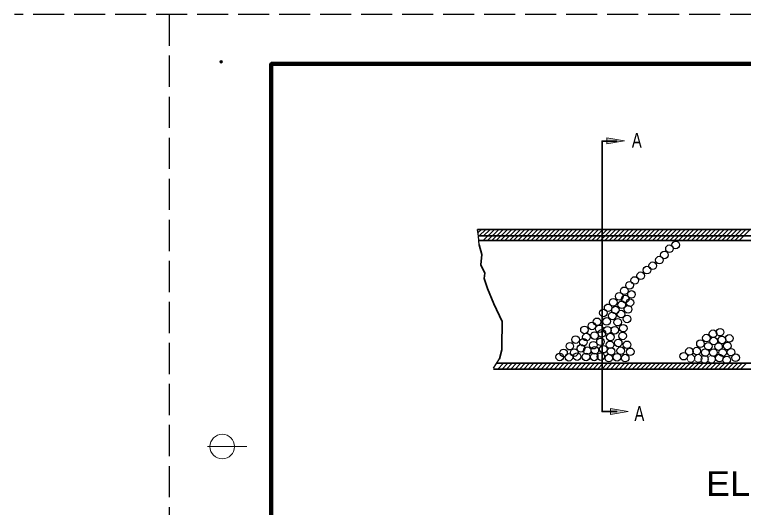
# Model space of a CAD drawing. Extents: x 36 to 71.3, y 0.3 to 22.3.
# Drawn here: x 35.97 to 43.4, y 17.3 to 22.32 of the extents above; entities that cross this region are included whole.
import ezdxf

# ---------------------------------------------------------------- set-up
doc = ezdxf.new("R2010")
doc.units = 0
doc.header["$LTSCALE"] = 0.053
doc.header["$PDMODE"] = 32
doc.header["$PDSIZE"] = 0.0265
doc.linetypes.add('LONG_DASHED', pattern=[7.5, 6, -1.5])
doc.layers.add('1', color=7, linetype='Continuous', lineweight=13)
doc.layers.add('2', color=7, linetype='Continuous', lineweight=13)

msp = doc.modelspace()

# ---------------------------------------------------------------- hatches: boundary and pattern name
at = {"layer": '2'}
for points in [[(42.00942, 21.06925), (42.00942, 21.00925), (42.18942, 21.03925), (42.18942, 21.03925)], [(42.04767, 18.31033), (42.04767, 18.25033), (42.22767, 18.28033), (42.22767, 18.28033)]]:
    msp.add_hatch(color=256, dxfattribs=at).paths.add_polyline_path(points)

# ---------------------------------------------------------------- linework, layer by layer
at = {"layer": '1', "linetype": 'LONG_DASHED', "lineweight": 25}
for p, q in [((71.17325, 22.32408), (35.97325, 22.32408)), ((37.54825, 22.32408), (37.54825, 0.32408))]:
    msp.add_line(p, q, dxfattribs=at)
at = {"layer": '1', "lineweight": 158}
for p, q in [((38.58992, 21.82408), (38.58992, 0.82408)), ((52.503, 21.82408), (38.58992, 21.82408))]:
    msp.add_line(p, q, dxfattribs=at)
at = {"layer": '1', "lineweight": 35}
for p, q in [((40.6925, 20.13667), (48.36025, 20.13667)), ((40.70233, 20.07117), (45.51333, 20.07117)), ((40.71125, 20.024), (45.51333, 20.024)), ((43.68442, 18.77233), (40.88925, 18.77233)), ((43.65142, 18.7125), (40.85458, 18.7125))]:
    msp.add_line(p, q, dxfattribs=at)
at = {"layer": '1', "lineweight": 25}
for p, q in [((40.698, 20.10333), (40.73142, 20.13667)), ((40.71008, 20.07117), (40.77558, 20.13667)), ((40.75133, 20.024), (40.864, 20.13667)), ((40.75425, 20.07117), (40.81975, 20.13667)), ((40.7955, 20.024), (40.90817, 20.13667)), ((40.83967, 20.024), (40.95233, 20.13667)), ((40.88392, 20.024), (40.99658, 20.13667)), ((40.92808, 20.024), (41.04075, 20.13667)), ((40.97225, 20.024), (41.08492, 20.13667)), ((41.0165, 20.024), (41.12917, 20.13667)), ((41.06067, 20.024), (41.17333, 20.13667)), ((41.10483, 20.024), (41.2175, 20.13667)), ((41.14908, 20.024), (41.26175, 20.13667)), ((41.19325, 20.024), (41.30592, 20.13667)), ((41.23742, 20.024), (41.35008, 20.13667)), ((41.28158, 20.024), (41.39425, 20.13667)), ((41.32583, 20.024), (41.4385, 20.13667)), ((41.37, 20.024), (41.48267, 20.13667)), ((41.41417, 20.024), (41.52683, 20.13667)), ((41.45842, 20.024), (41.57108, 20.13667)), ((41.50258, 20.024), (41.61525, 20.13667)), ((41.54675, 20.024), (41.65942, 20.13667)), ((41.591, 20.024), (41.70367, 20.13667)), ((41.63517, 20.024), (41.74783, 20.13667)), ((41.67933, 20.024), (41.792, 20.13667)), ((41.72358, 20.024), (41.83625, 20.13667)), ((41.76775, 20.024), (41.88042, 20.13667)), ((41.81192, 20.024), (41.92458, 20.13667)), ((41.85617, 20.024), (41.96883, 20.13667)), ((41.90033, 20.024), (42.013, 20.13667)), ((41.9445, 20.024), (42.05717, 20.13667)), ((41.98875, 20.024), (42.10142, 20.13667)), ((42.03292, 20.024), (42.14558, 20.13667)), ((42.07708, 20.024), (42.18975, 20.13667)), ((42.12133, 20.024), (42.234, 20.13667)), ((42.1655, 20.024), (42.27817, 20.13667)), ((42.20967, 20.024), (42.32233, 20.13667)), ((42.25392, 20.024), (42.36658, 20.13667)), ((42.29808, 20.024), (42.41075, 20.13667)), ((42.34225, 20.024), (42.45492, 20.13667)), ((42.3865, 20.024), (42.49917, 20.13667)), ((42.43067, 20.024), (42.54333, 20.13667)), ((42.47483, 20.024), (42.5875, 20.13667)), ((42.51908, 20.024), (42.63175, 20.13667)), ((42.56325, 20.024), (42.67592, 20.13667)), ((42.60742, 20.024), (42.72008, 20.13667)), ((42.65167, 20.024), (42.76433, 20.13667)), ((42.69583, 20.024), (42.8085, 20.13667)), ((42.74, 20.024), (42.85267, 20.13667)), ((42.78425, 20.024), (42.89692, 20.13667)), ((42.82842, 20.024), (42.94108, 20.13667)), ((42.87258, 20.024), (42.98525, 20.13667)), ((42.91683, 20.024), (43.0295, 20.13667)), ((42.961, 20.024), (43.07367, 20.13667)), ((43.00517, 20.024), (43.11783, 20.13667)), ((43.04942, 20.024), (43.16208, 20.13667)), ((43.09358, 20.024), (43.20625, 20.13667)), ((43.13775, 20.024), (43.25042, 20.13667)), ((43.182, 20.024), (43.29467, 20.13667)), ((43.22617, 20.024), (43.33883, 20.13667)), ((43.27033, 20.024), (43.383, 20.13667)), ((43.31458, 20.024), (43.42725, 20.13667)), ((43.35875, 20.024), (43.47142, 20.13667)), ((40.85458, 18.724), (40.91533, 18.81817)), ((40.89817, 18.7125), (40.958, 18.77233)), ((40.94242, 18.7125), (41.00225, 18.77233)), ((40.98658, 18.7125), (41.04642, 18.77233)), ((41.03075, 18.7125), (41.09058, 18.77233)), ((41.075, 18.7125), (41.13483, 18.77233)), ((41.11917, 18.7125), (41.179, 18.77233)), ((41.16333, 18.7125), (41.22317, 18.77233)), ((41.20758, 18.7125), (41.26742, 18.77233)), ((41.25175, 18.7125), (41.31158, 18.77233)), ((41.29592, 18.7125), (41.35575, 18.77233)), ((41.34017, 18.7125), (41.4, 18.77233)), ((41.38433, 18.7125), (41.44417, 18.77233)), ((41.4285, 18.7125), (41.48833, 18.77233)), ((41.47275, 18.7125), (41.53258, 18.77233)), ((41.51692, 18.7125), (41.57675, 18.77233)), ((41.56108, 18.7125), (41.62092, 18.77233)), ((41.60533, 18.7125), (41.66517, 18.77233)), ((41.6495, 18.7125), (41.70933, 18.77233)), ((41.69367, 18.7125), (41.7535, 18.77233)), ((41.73792, 18.7125), (41.79775, 18.77233)), ((41.78208, 18.7125), (41.84192, 18.77233)), ((41.82625, 18.7125), (41.88608, 18.77233)), ((41.8705, 18.7125), (41.93033, 18.77233)), ((41.91467, 18.7125), (41.9745, 18.77233)), ((41.95883, 18.7125), (42.01867, 18.77233)), ((42.00308, 18.7125), (42.06292, 18.77233)), ((42.04725, 18.7125), (42.10708, 18.77233)), ((42.09142, 18.7125), (42.15125, 18.77233)), ((42.13567, 18.7125), (42.1955, 18.77233)), ((42.17983, 18.7125), (42.23967, 18.77233)), ((42.224, 18.7125), (42.28383, 18.77233)), ((42.26825, 18.7125), (42.32808, 18.77233)), ((42.31242, 18.7125), (42.37225, 18.77233)), ((42.35658, 18.7125), (42.41642, 18.77233)), ((42.40083, 18.7125), (42.46067, 18.77233)), ((42.445, 18.7125), (42.50483, 18.77233)), ((42.48917, 18.7125), (42.549, 18.77233)), ((42.53342, 18.7125), (42.59317, 18.77233)), ((42.57758, 18.7125), (42.63742, 18.77233)), ((42.62175, 18.7125), (42.68158, 18.77233)), ((42.666, 18.7125), (42.72575, 18.77233)), ((42.71017, 18.7125), (42.77, 18.77233)), ((42.75433, 18.7125), (42.81417, 18.77233)), ((42.79858, 18.7125), (42.85833, 18.77233)), ((42.84275, 18.7125), (42.90258, 18.77233)), ((42.88692, 18.7125), (42.94675, 18.77233)), ((42.93117, 18.7125), (42.99092, 18.77233)), ((42.97533, 18.7125), (43.03517, 18.77233)), ((43.0195, 18.7125), (43.07933, 18.77233)), ((43.06375, 18.7125), (43.1235, 18.77233)), ((43.10792, 18.7125), (43.16775, 18.77233)), ((43.15208, 18.7125), (43.21192, 18.77233)), ((43.19633, 18.7125), (43.25608, 18.77233)), ((43.2405, 18.7125), (43.30033, 18.77233)), ((43.28467, 18.7125), (43.3445, 18.77233)), ((43.32892, 18.7125), (43.38867, 18.77233)), ((43.37308, 18.7125), (43.43292, 18.77233))]:
    msp.add_line(p, q, dxfattribs=at)
at = {"layer": '1'}
msp.add_line((38.33992, 17.92408), (37.93992, 17.92408), dxfattribs=at)
at = {"layer": '1', "lineweight": 25}
msp.add_lwpolyline([(40.70875, 19.9775), (40.7035, 20.06792), (40.69308, 20.13533)], dxfattribs=at)
at = {"layer": '1', "lineweight": 35}
msp.add_lwpolyline([(40.91533, 18.81817), (40.94133, 18.9085), (40.94133, 18.99125), (40.94133, 19.02175), (40.94483, 19.1185), (40.94483, 19.19867), (40.858, 19.37808), (40.79375, 19.53342), (40.76083, 19.63517), (40.76775, 19.69117), (40.72608, 19.77392), (40.73475, 19.87958), (40.70875, 19.9775)], dxfattribs=at)
at = {"layer": '1', "lineweight": 25}
for centre in [(42.71308, 19.9775), (42.59675, 19.87575), (42.64883, 19.93933), (42.54642, 19.82358), (42.47867, 19.76625), (42.35542, 19.6645), (42.41967, 19.72175), (42.29467, 19.61608), (42.18875, 19.5105), (42.24258, 19.5665), (42.13667, 19.4545), (42.19742, 19.42775), (42.26167, 19.47358), (42.07592, 19.39342), (42.16267, 19.36792), (42.246, 19.39083), (41.97517, 19.28525), (42.02383, 19.33742), (42.0985, 19.3145), (42.22692, 19.32208), (42.0655, 19.25467), (42.15575, 19.27375), (42.2165, 19.22417), (41.85892, 19.15283), (41.911, 19.19483), (42.00817, 19.19867), (42.121, 19.191), (42.17833, 19.12992), (41.7825, 19.11217), (41.9335, 19.12358), (41.95958, 19.07775), (42.01683, 19.10833), (42.0915, 19.10833), (43.09325, 19.07392), (43.16442, 19.08925), (41.69225, 19.01417), (41.77208, 18.98742), (41.80158, 19.03958), (41.88492, 19.05483), (41.94567, 18.99125), (42.04642, 19.03958), (42.17142, 19.05108), (43.02558, 19.02942), (43.10017, 18.99883), (43.1835, 19.01033), (43.25817, 19.02558), (41.63317, 18.94667), (41.746, 18.92375), (41.87275, 18.95683), (41.97517, 18.91617), (42.04292, 18.96067), (42.12625, 18.97975), (42.2165, 18.96067), (42.96475, 18.97217), (43.04467, 18.94667), (43.14883, 18.94283), (43.23908, 18.94925), (41.53075, 18.83725), (41.56892, 18.878), (41.6245, 18.83342), (41.67833, 18.88175), (41.70783, 18.84108), (41.79808, 18.83725), (41.81025, 18.90083), (41.88142, 18.83725), (41.88842, 18.90467), (41.94917, 18.84108), (42.05333, 18.89325), (42.11408, 18.83342), (42.15225, 18.90083), (42.2495, 18.88942), (42.79467, 18.84483), (42.85192, 18.89325), (42.92658, 18.89708), (43.01342, 18.88175), (43.09675, 18.88175), (43.1905, 18.88175), (43.27725, 18.88558), (42.03075, 18.82575), (42.19742, 18.82575), (43.1575, 18.82575), (43.23217, 18.80667), (43.32242, 18.82958)]:
    msp.add_circle(centre, 0.03866, dxfattribs=at)
at = {"layer": '1'}
for centre, radius in [((42.86758, 18.822), 0.03866), ((42.94225, 18.822), 0.03866), ((43.00642, 18.81433), 0.03866), ((43.07767, 18.81433), 0.03866), ((38.08992, 17.92408), 0.125)]:
    msp.add_circle(centre, radius, dxfattribs=at)
for p in [(38.07792, 21.84408), (38.58992, 21.82408)]:
    msp.add_point(p, dxfattribs=at)
at = {"layer": '2', "lineweight": 35}
msp.add_lwpolyline([(42.11492, 21.03567), (41.96117, 21.03567), (41.96117, 18.28033), (42.11492, 18.28033)], dxfattribs=at)
at = {"layer": '2'}
for points in [[(42.00942, 21.06925), (42.00942, 21.00925), (42.18942, 21.03925), (42.18942, 21.03925)], [(42.04767, 18.31033), (42.04767, 18.25033), (42.22767, 18.28033), (42.22767, 18.28033)]]:
    msp.add_lwpolyline(points, close=True, dxfattribs=at)

# ---------------------------------------------------------------- texts
for s, height, width, p in [('A', 0.15, 0.75, (42.26542, 20.96933)), ('A', 0.15, 0.75, (42.29183, 18.18608)), ('ELEVATION VIEW', 0.25, 1.1, (43.02083, 17.422))]:
    msp.add_text(s, height=height, dxfattribs=dict(at, width=width)).set_placement(p)

doc.saveas('drawing.dxf')
